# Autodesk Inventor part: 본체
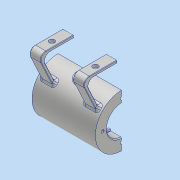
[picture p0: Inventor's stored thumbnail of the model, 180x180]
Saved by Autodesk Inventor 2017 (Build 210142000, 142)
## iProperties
Part Number: 본체
Material: 알루미늄 6061
Document SubType Name: Modeling
Designer: Administrator
Density: 2.7 g/cm^3
Appearance: 알루미늄 - 평지
Mass: 312.239 g
Surface Area: 354.619 cm^2
Volume: 115.644 cm^3
Author: Administrator
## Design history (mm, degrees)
sketch "스케치3"
  geometry: L1 (0, 29)-(35, 29); L2 (35, 29)-(35, 16); L3 (35, 16)-(23, 16); L4 (23, 16)-(23, 14); L5 (23, 14)-(21, 14); L6 (21, 14)-(21, 21); L7 (21, 21)-(0, 21); L8 (0, 21)-(0, 29); L9 (-7, 0)-(42, 0) reference; 1 further point
  constraints: 16 end point, 5 perpendicular, 1 horizontal, 1 parallel, 1 vertical, 1 vertical alignment
  dimensions: "d19" = 35 distance between parallel lines of L2 L8; "d20" = 12 distance of L2.end L3.end; "d21" = 2 distance of L4.end L5.end; "d22" = 16 distance from line of point (0, 0) L3; "d23" = 14 distance from line of point (0, 0) L5; "d24" = 21 distance from line of point (0, 0) L7; "d25" = 29 distance from line of point (0, 0) L1
revolve "회전1" sketch "스케치3" stored, may be unused: angle "d26" = 90 deg
sketch "스케치4" dims "d27" = 42
  geometry: 3 further points
  constraints: 2 vertical alignment, 1 coincident, 2 other
hole "구멍1" sketch "스케치4" at (0, 21) diameter "d28" = 3.242; stored, may be unused: countersink angle "d32" = 90 deg, drill point angle "d34" = 118 deg; dims "d29" = 8, "d30" = 4, "d31" = 2, "d33" = 10
node "작업 평면1"
sketch "스케치5"
  geometry: C1 r 5 at (0, 0); 1 further point
  constraints: 1 centre point, 1 coincident
  dimensions: "d39" = 10 diameter of C1
extrude "돌출1" join sketch "스케치5" stored distance "d40" = 10; taper "d41" = 0 deg
sketch "스케치6"
  geometry: 2 further points
  constraints: 1 coincident
hole "구멍2" sketch "스케치6" at (0, 0) diameter "d42" = 5.188; stored, may be unused: countersink angle "d46" = 90 deg, drill point angle "d48" = 118 deg; dims "d43" = 6, "d44" = 4, "d45" = 2, "d47" = 8
sketch "스케치7"
  geometry: C1 r 1.5 at (0, 0); 1 further point
  constraints: 1 centre point, 1 coincident
  dimensions: "d49" = 3 diameter of C1
extrude "돌출2" cut sketch "스케치7" distance "d50" = 24.75; taper "d51" = 0 deg
node "작업 평면2"
node "작업 평면3"
sketch "스케치9"
  geometry: L1 (55, 40.6)-(55, -40.6) reference; L2 (55, -40)-(55, 40); L3 (17.993, 22.743)-(55, 40); L4 (17.993, -22.743)-(55, -40); L5 (20.438, -20.574)-(52, -35.291); L6 (52, -35.291)-(52, 35.291); L7 (52, 35.291)-(20.438, 20.574); C1 r 1.621 at (-21, 0) reference; C2 r 1.621 at (0, -21) reference; C3 r 1.621 at (21, 0) reference; C4 r 1.621 at (0, 21) reference; C5 r 16 at (0, 0) reference; A1 r 29 centre (0, 0) between (17.993, 22.743) and (17.993, -22.743) reference; A2 r 29 centre (0, 0) between (17.993, 22.743) and (17.993, -22.743) reference; 1 further point
  constraints: 12 end point, 6 point on circle, 2 parallel, 2 point on line
  dimensions: "d54" = 80 distance of L2.end L2.start; "d55" = 40 vertical distance of C3.centre L2.start; "d56" = 65 deg angle of L1 L4; "d57" = 65 deg angle of L1 L3; "d59" = 3 distance between parallel lines of L4 L5; "d62" = 3 distance between parallel lines of L1 L6; "d63" = 3 distance between parallel lines of L3 L7
extrude "돌출3" join sketch "스케치9" distance "d64" = 12; taper "d65" = 0 deg
sketch "스케치10"
  geometry: L1 (0, 0)-(0, 29); L2 (0, 0)-(-10.945, 30.07); 1 further point
  constraints: 4 end point, 1 vertical, 1 vertical alignment, 1 other
  dimensions: "d68" = 20 deg angle of L2 L1; "d69" = 32 distance of L2.end point (0, 0)
node "작업 평면5"
sketch "스케치11"
  geometry: C1 r 6 at (0, 0); 1 further point
  constraints: 1 centre point, 1 coincident
  dimensions: "d70" = 12 diameter of C1
extrude "돌출4" join sketch "스케치11" stored distance "d71" = 12; taper "d72" = 0 deg
sketch "스케치12"
  geometry: 2 further points
  constraints: 1 coincident
hole "구멍3" sketch "스케치12" at (0, 0) diameter "d73" = 5.188; stored, may be unused: countersink angle "d77" = 90 deg, drill point angle "d79" = 118 deg; dims "d74" = 20, "d75" = 4, "d76" = 2, "d78" = 20.5
sketch "스케치13"
  geometry: L1 (0, 0)-(0, 80) reference; L2 (0, 0)-(12, 0) reference; C1 r 3 at (6, 58); 1 further point
  constraints: 1 centre point
  dimensions: "d80" = 6 diameter of C1; "d81" = 6 distance from line of C1.centre L1; "d82" = 18 vertical distance of point (30, 40) C1.centre
extrude "돌출5" cut sketch "스케치13" distance "d83" = 11.75; taper "d84" = 0 deg
fillet "모깎기1" dims "d91" = 6
fillet "모깎기2" dims "d92" = 0.5
fillet "모깎기3" dims "d93" = 3
fillet "모깎기4" dims "d94" = 0.3
fillet "모깎기5" dims "d95" = 1
fillet "모깎기6" dims "d96" = 1
node "작업 평면6"
sketch "스케치14"
  geometry: L1 (35, 29)-(35, -29) reference; L2 (35, -29)-(-35, -29) reference; 2 further points
  constraints: 1 other
  dimensions: "d98" = 35 distance from line of point (0, 0) L1; "d99" = 29 distance from line of point (0, 0) L2
feature "엠보싱1" sketch "스케치14" dims "d19" = 35, "d20" = 12, "d21" = 2, "d22" = 16, "d23" = 14, "d24" = 21, "d25" = 29, "d100" = 0.5, "d101" = 0
chamfer "모따기1" distance "d102" = 1; stored, may be unused: second distance "d103" = 2, angle "d104" = 45 deg
fillet "모깎기7" dims "d105" = 3
node "솔리드1"
pattern_circular "원형 패턴1" dims angle "d36" = 360 deg
mirror "미러1"
mirror "미러2"
pattern_linear "직사각형 패턴1" dims "d87" = 36, "d90" = 48
node "투영된 루프1"
other parameters: "d38" = -32, "d52" = 55, "d53" = -5, "d97" = 29
